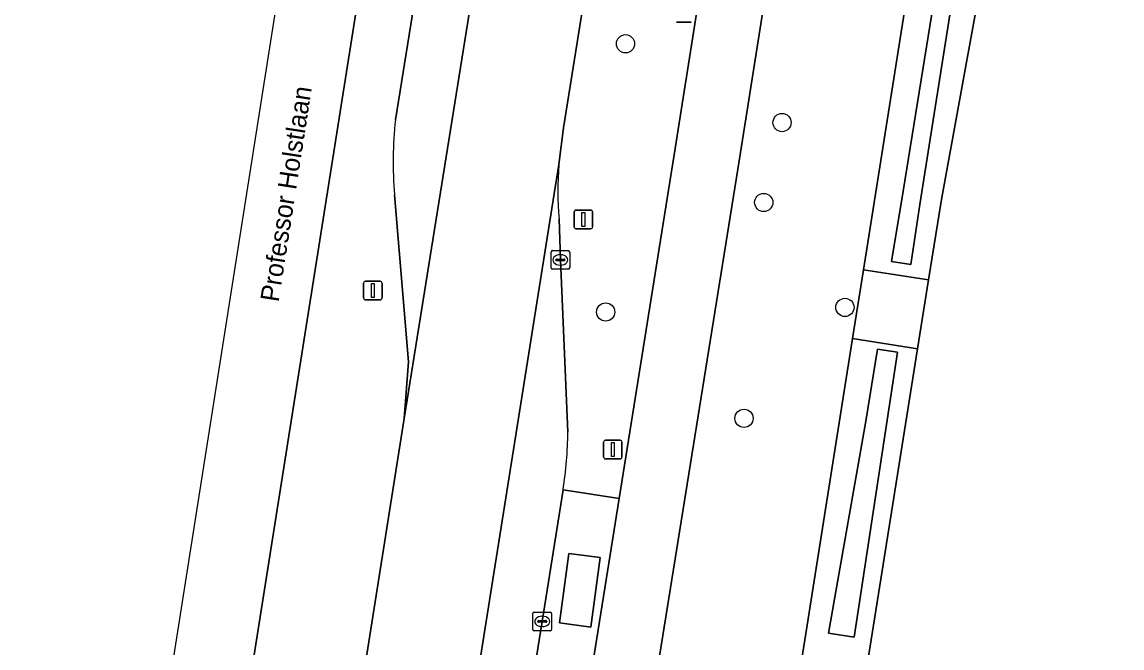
# Model space of a CAD drawing. Extents: x 160203 to 161530, y 379528 to 381797.
# Drawn here: x 160307.5 to 160366.6, y 380365.5 to 380399.1 of the extents above; entities that cross this region are included whole.
import ezdxf

# ---------------------------------------------------------------- set-up
doc = ezdxf.new("R2010")
doc.units = 0
for name, color, linetype in [('IMGEO_Berm_groen', 7, 'Continuous'), ('IMGEO_Boom', 7, 'Continuous'), ('IMGEO_Fietspad_gesloten', 7, 'Continuous'), ('IMGEO_Grasland_agrarisch', 7, 'Continuous'), ('IMGEO_Groenvoorziening', 7, 'Continuous'), ('IMGEO_Kolk', 7, 'Continuous'), ('IMGEO_Lichtmast', 7, 'Continuous'), ('IMGEO_Oever', 7, 'Continuous'), ('IMGEO_Openbare_ruimte_label', 7, 'Continuous'), ('IMGEO_OVBaan_gesloten', 7, 'Continuous'), ('IMGEO_Rijbaan_regionaal_gesloten', 7, 'Continuous'), ('IMGEO_Verkeersbordpaal', 7, 'Continuous'), ('IMGEO_Voetpad_gesloten', 7, 'Continuous'), ('IMGEO_Voetpad_open', 7, 'Continuous'), ('IMGEO_Waterloop', 7, 'Continuous')]:
    doc.layers.add(name, color=color, linetype=linetype)

msp = doc.modelspace()

# ---------------------------------------------------------------- linework, layer by layer
at = {"layer": 'IMGEO_Berm_groen'}
for points in [[(160380.205, 380606.406), (160371.189, 380549.526), (160367.433, 380526.109), (160363.246, 380500), (160361.784, 380490.887), (160355.339, 380450.611), (160346.029, 380391.769), (160338.96, 380347.733), (160332.907, 380309.531), (160331.544, 380300.93), (160328.424, 380281.305)], [(160358.293, 380491.158), (160359.706, 380500), (160363.967, 380526.659), (160367.706, 380550.056), (160374.855, 380595.163), (160367.388, 380586.261), (160364.666, 380569.299), (160361.773, 380551.056), (160358.549, 380530.801), (160358.035, 380527.602), (160355.297, 380510.581), (160353.625, 380500), (160352.416, 380492.353), (160349.015, 380471.121), (160345.925, 380451.876), (160342.705, 380431.641), (160336.593, 380393.432), (160336.341, 380391.468)], [(160334.043, 380268.351), (160340.373, 380308.236), (160348.502, 380359.458), (160349.372, 380364.94), (160352.1, 380382.133), (160352.684, 380385.815), (160356.287, 380408.516), (160361.612, 380442.808), (160363.62, 380454.848), (160364.253, 380457.684), (160365.385, 380465.491), (160366.679, 380472.607), (160367.782, 380480.751), (160370.802, 380500), (160371.249, 380502.852)], [(160336.565, 380374.023), (160339.578, 380373.55), (160342.587, 380392.328), (160351.85, 380450.983), (160358.293, 380491.158)], [(160328.155, 380416.671), (160317.914, 380352.077), (160315.52, 380337.005), (160319.87, 380326.164), (160323.805, 380351.043), (160328.049, 380377.845)], [(160327.57, 380393.867), (160330.43, 380411.684)], [(160328.049, 380377.845), (160328.276, 380380.878), (160327.524, 380389.85)], [(160336.351, 380388.549), (160336.423, 380386.35), (160336.819, 380377.111)]]:
    msp.add_lwpolyline(points, dxfattribs=at)
for centre, radius, start, end in [((160347.871, 380391.626), 20.424, 173.69997, 184.98786), ((160355.003, 380390.072), 18.714, 175.72316, 184.66941), ((160318.093, 380377.097), 18.726, 350.55219, 0.04338)]:
    msp.add_arc(centre, radius, start, end, dxfattribs=at)
at = {"layer": 'IMGEO_Boom'}
for centre in [(160339.919, 380397.949), (160348.319, 380393.722), (160347.336, 380389.435), (160338.851, 380383.555), (160351.691, 380383.802), (160346.279, 380377.851)]:
    msp.add_circle(centre, 0.489, dxfattribs=at)
at = {"layer": 'IMGEO_Fietspad_gesloten'}
msp.add_lwpolyline([(160338.96, 380347.733), (160346.029, 380391.769), (160355.339, 380450.611), (160351.85, 380450.983), (160342.587, 380392.328), (160339.578, 380373.55), (160329.428, 380310.134), (160332.907, 380309.531)], close=True, dxfattribs=at)
at = {"layer": 'IMGEO_Grasland_agrarisch'}
msp.add_lwpolyline([(160391.591, 380603.409), (160387.523, 380579.574), (160379.296, 380526.737), (160378.851, 380524.294), (160377.634, 380517.623), (160376.818, 380512.224), (160375.308, 380502.238), (160374.97, 380500), (160372.848, 380488.626), (160370.146, 380472.104), (160369.369, 380465.742), (160366.989, 380450.176), (160364.586, 380436.343), (160363.043, 380425.732), (160361.825, 380419.072), (160360.362, 380409.1), (160358.765, 380400.008), (160356.87, 380389.591), (160356.183, 380385.289), (160355.589, 380381.575), (160352.843, 380364.39), (160351.967, 380358.904), (160343.777, 380307.646), (160335.794, 380257.683)], dxfattribs=at)
at = {"layer": 'IMGEO_Groenvoorziening'}
msp.add_lwpolyline([(160356.183, 380385.289), (160352.684, 380385.815), (160352.1, 380382.133), (160355.589, 380381.575)], close=True, dxfattribs=at)
at = {"layer": 'IMGEO_Kolk'}
for p, q in [((160335.923, 380385.924), (160335.923, 380386.776)), ((160335.998, 380386.85), (160336.85, 380386.85)), ((160336.924, 380386.776), (160336.924, 380385.924)), ((160336.182, 380386.344), (160336.182, 380386.356)), ((160336.62, 380386.307), (160336.222, 380386.307)), ((160336.225, 380386.393), (160336.623, 380386.393)), ((160336.411, 380386.63), (160336.436, 380386.63)), ((160336.666, 380386.356), (160336.666, 380386.344)), ((160336.85, 380385.85), (160335.998, 380385.85)), ((160336.434, 380386.07), (160336.409, 380386.07)), ((160334.946, 380366.527), (160334.946, 380367.379)), ((160335.021, 380367.453), (160335.873, 380367.453)), ((160335.434, 380367.233), (160335.459, 380367.233)), ((160335.947, 380367.379), (160335.947, 380366.527)), ((160335.205, 380366.947), (160335.205, 380366.959)), ((160335.643, 380366.91), (160335.245, 380366.91)), ((160335.248, 380366.996), (160335.646, 380366.996)), ((160335.457, 380366.673), (160335.432, 380366.673)), ((160335.689, 380366.959), (160335.689, 380366.947)), ((160335.873, 380366.453), (160335.021, 380366.453))]:
    msp.add_line(p, q, dxfattribs=at)
for points in [[(160335.923, 380385.924), (160335.923, 380386.776)], [(160335.998, 380386.85), (160336.85, 380386.85)], [(160336.924, 380386.776), (160336.924, 380385.924)], [(160336.85, 380385.85), (160335.998, 380385.85)], [(160334.946, 380366.527), (160334.946, 380367.379)], [(160335.021, 380367.453), (160335.873, 380367.453)], [(160335.947, 380367.379), (160335.947, 380366.527)], [(160335.873, 380366.453), (160335.021, 380366.453)]]:
    msp.add_lwpolyline(points, dxfattribs=at)
for centre, radius, start, end in [((160336, 380386.774), 0.0765, 91.55205, 178.44795), ((160336, 380386.774), 0.0765, 91.55205, 178.44795), ((160336.848, 380386.774), 0.0765, 1.55205, 88.44795), ((160336.848, 380386.774), 0.0765, 1.55205, 88.44795), ((160336.222, 380386.353), 0.0403, 85.87752, 175.75265), ((160336.219, 380386.343), 0.0366, 178.93798, 274.71019), ((160336.623, 380386.35), 0.043, 264.86636, 352.45326), ((160336.627, 380386.355), 0.0386, 1.73085, 96.63898), ((160336, 380385.926), 0.0765, 181.55205, 268.44795), ((160336, 380385.926), 0.0765, 181.55205, 268.44795), ((160336.848, 380385.926), 0.0765, 271.55205, 358.44795), ((160336.848, 380385.926), 0.0765, 271.55205, 358.44795), ((160335.023, 380367.377), 0.0765, 91.55205, 178.44795), ((160335.023, 380367.377), 0.0765, 91.55205, 178.44795), ((160335.871, 380367.377), 0.0765, 1.55205, 88.44795), ((160335.871, 380367.377), 0.0765, 1.55205, 88.44795), ((160335.245, 380366.956), 0.0403, 85.87752, 175.75265), ((160335.242, 380366.946), 0.0366, 178.93798, 274.71019), ((160335.646, 380366.953), 0.043, 264.86636, 352.45326), ((160335.65, 380366.958), 0.0386, 1.73085, 96.63898), ((160335.023, 380366.529), 0.0765, 181.55205, 268.44795), ((160335.023, 380366.529), 0.0765, 181.55205, 268.44795), ((160335.871, 380366.529), 0.0765, 271.55205, 358.44795), ((160335.871, 380366.529), 0.0765, 271.55205, 358.44795)]:
    msp.add_arc(centre, radius, start, end, dxfattribs=at)
for centre, major_axis, ratio, start_param, end_param in [((160336.41, 380386.35), (-0.387, 0.002), 0.722429, 4.712389, 7.853982), ((160336.435, 380386.35), (-0.39, 0.002), 0.717154, 1.570796, 4.712389), ((160335.433, 380366.953), (-0.387, 0.002), 0.722429, 4.712389, 7.853982), ((160335.458, 380366.953), (-0.39, 0.002), 0.717154, 1.570796, 4.712389)]:
    msp.add_ellipse(centre, major_axis=major_axis, ratio=ratio, start_param=start_param, end_param=end_param, dxfattribs=at)
at = {"layer": 'IMGEO_Lichtmast'}
for p, q in [((160343.438, 380399.117), (160342.648, 380399.117)), ((160342.648, 380399.117), (160343.438, 380399.117)), ((160325.866, 380384.308), (160325.866, 380385.108)), ((160325.866, 380385.108), (160325.866, 380384.308)), ((160325.966, 380385.208), (160326.756, 380385.208)), ((160326.756, 380385.208), (160325.966, 380385.208)), ((160326.856, 380385.108), (160326.856, 380384.308)), ((160326.856, 380384.308), (160326.856, 380385.108)), ((160326.756, 380384.208), (160325.966, 380384.208)), ((160325.966, 380384.208), (160326.756, 380384.208)), ((160338.838, 380376.677), (160339.628, 380376.677)), ((160339.628, 380376.677), (160338.838, 380376.677)), ((160338.738, 380375.777), (160338.738, 380376.577)), ((160338.738, 380376.577), (160338.738, 380375.777)), ((160339.728, 380376.577), (160339.728, 380375.777)), ((160339.728, 380375.777), (160339.728, 380376.577)), ((160339.628, 380375.677), (160338.838, 380375.677)), ((160338.838, 380375.677), (160339.628, 380375.677))]:
    msp.add_line(p, q, dxfattribs=at)
for points in [[(160326.286, 380385.083), (160326.436, 380385.083), (160326.436, 380384.333), (160326.286, 380384.333), (160326.286, 380385.083)], [(160339.158, 380376.552), (160339.308, 380376.552), (160339.308, 380375.802), (160339.158, 380375.802), (160339.158, 380376.552)]]:
    msp.add_lwpolyline(points, dxfattribs=at)
for centre, start, end in [((160325.966, 380385.108), 90, 180), ((160325.966, 380385.108), 90, 180), ((160326.756, 380385.108), 0, 90), ((160326.756, 380385.108), 360, 90), ((160325.966, 380384.308), 180, 270), ((160325.966, 380384.308), 180, 270), ((160326.756, 380384.308), 270, 0), ((160326.756, 380384.308), 270, 0), ((160338.838, 380376.577), 90, 180), ((160338.838, 380376.577), 90, 180), ((160339.628, 380376.577), 0, 90), ((160339.628, 380376.577), 360, 90), ((160338.838, 380375.777), 180, 270), ((160338.838, 380375.777), 180, 270), ((160339.628, 380375.777), 270, 0), ((160339.628, 380375.777), 270, 0)]:
    msp.add_arc(centre, 0.1, start, end, dxfattribs=at)
at = {"layer": 'IMGEO_Oever'}
for points in [[(160390.283, 380602.648), (160386, 380577.395), (160377.268, 380524.546), (160375.458, 380513.613), (160373.434, 380501.388), (160370.437, 380483.285), (160366.048, 380454.705), (160360.368, 380418.754), (160355.719, 380389.323), (160355.227, 380386.102), (160354.2, 380386.268), (160354.809, 380390.039), (160357.778, 380408.419), (160361.753, 380433.029), (160367.445, 380469.514), (160370.699, 380490.376), (160372.531, 380501.536), (160374.537, 380513.764), (160376.097, 380523.266)], [(160371.249, 380502.852), (160370.802, 380500), (160367.782, 380480.751), (160366.679, 380472.607), (160365.385, 380465.491), (160364.253, 380457.684), (160363.62, 380454.848), (160361.612, 380442.808), (160356.287, 380408.516), (160352.684, 380385.815), (160356.183, 380385.289), (160356.87, 380389.591), (160358.765, 380400.008), (160360.362, 380409.1), (160361.825, 380419.072), (160363.043, 380425.732), (160364.586, 380436.343), (160366.989, 380450.176), (160369.369, 380465.742), (160370.146, 380472.104), (160372.848, 380488.626), (160374.97, 380500), (160375.308, 380502.238)]]:
    msp.add_lwpolyline(points, dxfattribs=at)
for points in [[(160355.589, 380381.575), (160352.1, 380382.133), (160349.372, 380364.94), (160352.843, 380364.39)], [(160352.18, 380366.115), (160350.809, 380366.324), (160352.815, 380377.697), (160353.441, 380381.571), (160354.51, 380381.398)]]:
    msp.add_lwpolyline(points, close=True, dxfattribs=at)
at = {"layer": 'IMGEO_OVBaan_gesloten'}
for points in [[(160336.341, 380391.468), (160324.382, 380316.217), (160325.3, 380319.901), (160327.151, 380326.513), (160330.821, 380339.612), (160331.689, 380343.518), (160332.509, 380348.694), (160335.445, 380366.954), (160336.565, 380374.023)], [(160336.819, 380377.111), (160336.423, 380386.35), (160336.351, 380388.549)]]:
    msp.add_lwpolyline(points, dxfattribs=at)
for centre, radius, start, end in [((160355.003, 380390.072), 18.714, 175.72316, 184.66941), ((160318.093, 380377.097), 18.726, 350.55219, 0.04338)]:
    msp.add_arc(centre, radius, start, end, dxfattribs=at)
at = {"layer": 'IMGEO_Rijbaan_regionaal_gesloten'}
msp.add_lwpolyline([(160307.532, 380313.4), (160308.269, 380313.283), (160311.667, 380312.745), (160315.52, 380337.005), (160317.914, 380352.077), (160328.155, 380416.671), (160330.069, 380428.623), (160330.26, 380429.737), (160341.49, 380500), (160346.119, 380528.965), (160346.201, 380529.483), (160352.778, 380570.911), (160356.772, 380595.979), (160359.064, 380610.365), (160354.423, 380611.084)], close=True, dxfattribs=at)
for points in [[(160349.462, 380512.028), (160347.546, 380500), (160336.207, 380428.804), (160335.344, 380423.335), (160328.049, 380377.845), (160323.805, 380351.043), (160319.87, 380326.164), (160317.621, 380311.944), (160323.486, 380310.927), (160323.63, 380311.821), (160323.997, 380314.024), (160324.382, 380316.217), (160336.341, 380391.468), (160336.593, 380393.432), (160342.705, 380431.641), (160345.925, 380451.876), (160349.015, 380471.121), (160352.416, 380492.353), (160353.625, 380500), (160355.297, 380510.581), (160358.035, 380527.602), (160358.549, 380530.801), (160361.773, 380551.056)], [(160327.524, 380389.85), (160328.276, 380380.878), (160328.049, 380377.845), (160335.344, 380423.335)], [(160330.43, 380411.684), (160327.57, 380393.867)]]:
    msp.add_lwpolyline(points, dxfattribs=at)
msp.add_arc((160347.871, 380391.626), 20.424, 173.69997, 184.98786, dxfattribs=at)
at = {"layer": 'IMGEO_Verkeersbordpaal'}
for p, q in [((160337.161, 380388.123), (160337.161, 380388.923)), ((160337.161, 380388.923), (160337.161, 380388.123)), ((160337.261, 380389.023), (160338.051, 380389.023)), ((160338.051, 380389.023), (160337.261, 380389.023)), ((160338.151, 380388.923), (160338.151, 380388.123)), ((160338.151, 380388.123), (160338.151, 380388.923)), ((160338.051, 380388.023), (160337.261, 380388.023)), ((160337.261, 380388.023), (160338.051, 380388.023))]:
    msp.add_line(p, q, dxfattribs=at)
msp.add_lwpolyline([(160337.581, 380388.898), (160337.731, 380388.898), (160337.731, 380388.148), (160337.581, 380388.148), (160337.581, 380388.898)], dxfattribs=at)
for centre, start, end in [((160337.261, 380388.923), 90, 180), ((160337.261, 380388.923), 90, 180), ((160338.051, 380388.923), 0, 90), ((160338.051, 380388.923), 360, 90), ((160337.261, 380388.123), 180, 270), ((160337.261, 380388.123), 180, 270), ((160338.051, 380388.123), 270, 0), ((160338.051, 380388.123), 270, 0)]:
    msp.add_arc(centre, 0.1, start, end, dxfattribs=at)
at = {"layer": 'IMGEO_Voetpad_gesloten'}
msp.add_lwpolyline([(160338.555, 380370.381), (160336.87, 380370.606), (160336.373, 380366.873), (160338.058, 380366.649)], close=True, dxfattribs=at)
at = {"layer": 'IMGEO_Voetpad_open'}
for points in [[(160339.578, 380373.55), (160336.565, 380374.023), (160335.445, 380366.954), (160332.509, 380348.694), (160331.689, 380343.518), (160330.821, 380339.612), (160327.151, 380326.513), (160328.836, 380326.217), (160326.268, 380310.176), (160328.885, 380309.769)], [(160329.428, 380310.134), (160339.578, 380373.55)]]:
    msp.add_lwpolyline(points, dxfattribs=at)
msp.add_lwpolyline([(160336.373, 380366.873), (160336.87, 380370.606), (160338.555, 380370.381), (160338.058, 380366.649)], close=True, dxfattribs=at)
at = {"layer": 'IMGEO_Waterloop'}
msp.add_lwpolyline([(160389.078, 380602.852), (160386.91, 380590.134), (160383.778, 380570.588), (160383.152, 380566.044), (160380.322, 380548.695), (160376.097, 380523.266), (160374.537, 380513.764), (160372.531, 380501.536), (160370.699, 380490.376), (160367.445, 380469.514), (160361.753, 380433.029), (160357.778, 380408.419), (160354.809, 380390.039), (160354.2, 380386.268), (160355.227, 380386.102), (160355.719, 380389.323), (160360.368, 380418.754), (160366.048, 380454.705), (160370.437, 380483.285), (160373.434, 380501.388), (160375.458, 380513.613), (160377.268, 380524.546), (160386, 380577.395)], dxfattribs=at)
msp.add_lwpolyline([(160354.51, 380381.398), (160353.441, 380381.571), (160352.815, 380377.697), (160350.809, 380366.324), (160352.18, 380366.115)], close=True, dxfattribs=at)

# ---------------------------------------------------------------- texts
at = {"layer": 'IMGEO_Openbare_ruimte_label'}
msp.add_text('Professor Holstlaan', height=1, rotation=81.1972, dxfattribs=at).set_placement((160321.303, 380384.057))

doc.saveas('drawing.dxf')
